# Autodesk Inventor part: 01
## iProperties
Created: 2012-02
Part Number: 01
Document SubType Name: Modeling
Density: 1 g/cm^3
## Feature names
1. Trennen1
2. Trennen2
3. Trennen3
4. Trennen4
5. Rundung2 [Fillet]
6. Rundung6 [Fillet]
7. Bohrung1 [Hole]
8. Spiegeln2 [Mirror]
9. Runde Anordnung2 [Circular Pattern]
